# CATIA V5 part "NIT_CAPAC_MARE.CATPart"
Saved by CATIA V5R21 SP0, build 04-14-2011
Part number: NIT MARE
Publications: "Mating Face", "Axis"
Bounding box of the stored display mesh (mm): x -64.5 to 6.58, y -7.5 to 7.5, z -8.66 to 8.66
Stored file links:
  C:\Users\MIRCEA\Desktop\MOM\Mogan\model\NIT_CAPAC_MARE.CATPart
  C:\Program Files (x86)\Dassault Systemes\B21\intel_a\startup\components\MechanicalStandardParts\EN_Standards\Design_Tables\EN_ISO_4014_GRADES_A_B_HEXAGON_HEAD_BOLT.txt
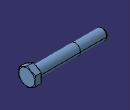
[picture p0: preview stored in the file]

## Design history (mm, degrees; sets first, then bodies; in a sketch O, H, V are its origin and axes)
Parameters
  d_dia = 10 mm
  l_length = 64.5 mm
  s_nom_across_flats = 15 mm
  k_max_head_depth = 6.58 mm
  dw_min = 14.5 mm
  r_min = 0.4 mm
  c_max = 0.6 mm
  p_pitch = 1.5 mm
  threading = 26 mm
Body1 "PartBody" (main body)
  Sketch1 on yz-plane, origin (0, 0, 0), H (0, 1, 0), V (0, 0, 1)
    circle A1 centre (0, 0) radius 7.25
    radius A1 = 7.25 {= dw_min /2}
  Pad1: profile Sketch1, direction (1, 0, 0), length 0.6 {= c_max}
  Sketch2 on face of Pad1, origin (0.6, 0, 0), H (0, 1, 0), V (0, 0, 1)
    point P1 (7.5, -4.3301)
    point P2 (7.5, 4.3301)
    point P3 (0, 8.6603)
    point P4 (-7.5, 4.3301)
    point P5 (-7.5, -4.3301)
    point P6 (0, -8.6603)
    point P7 (7.5, 0)
    line L1 (7.5, -4.3301) -> (7.5, 4.3301)
    line L2 (7.5, 4.3301) -> (0, 8.6603)
    line L3 (0, 8.6603) -> (-7.5, 4.3301)
    line L4 (-7.5, 4.3301) -> (-7.5, -4.3301)
    line L5 (-7.5, -4.3301) -> (0, -8.6603)
    line L6 (0, -8.6603) -> (7.5, -4.3301)
    construction line L7 (0, 0) -> (7.5, 0)
    construction circle A1 centre (0, 0) radius 8.6603
    construction arc A2 centre (-7.5, -4.3301) radius 8.6603 from (-7.5, 4.3301) to (0, -8.6603) cw
    construction arc A3 centre (7.5, 4.3301) radius 8.6603 from (0, 8.6603) to (7.5, -4.3301) ccw
    point P8 (-7.5, -4.3301)
    point P9 (7.5, 4.3301)
    distance L1 L4 = 15 {= s_nom_across_flats}
    horizontal: L7 H
    coincidence: A1 P1, A1 P2, A1 P3, A1 P4, A1 P5, A1 P6, A2 P4, A2 P6, A2 O, P8 P5, A3 P3, A3 P1, A3 O, P9 P2
    midpoint: P7 L1
  Pad2: profile Sketch2, direction (1, 0, 0), length 5.98 {= k_max_head_depth -c_max}
  Sketch3 on zx-plane, origin (0, 0, 0), H (-1, 0, 0), V (0, 0, 1)
    point P1 (-6.58, 7.4664)
    axis line L1 (-94.6904, 0) -> (76.7146, 0)
    reference intersected line E1 through (1000000, 0) direction (-1, 0) from xy-plane
    line L2 (-5.8907, 8.6603) -> (-6.58, 7.4664)
    line L3 (-5.8907, 8.6603) -> (-6.58, 8.6603)
    line L4 (-6.58, 8.6603) -> (-6.58, 7.4664)
    reference projected line E2 (-0.8, 8.6603) -> (-18.28, 8.6603) from edge [face of Pad2 | face of Pad2]
    distance P1 H = 7.4664 {= s_nom_across_flats /2.009}
    distance P1 V = 6.58 {= k_max_head_depth}
    angle L4 L2 = 30
    horizontal: L1 H, L3 H
    coincidence: L1 E1, L3 E2
    vertical: L4 V
  Groove1: profile Sketch3, axis Sketch3.L1, angle 360
  Sketch4 on face of Pad1, origin (0, 0, 0), H (0, -1, 0), V (0, 0, 1)
    circle A1 centre (0, 0) radius 5
    radius A1 = 5 {= d_dia /2}
  Pad3: profile Sketch4, direction (-1, 0, 0), length 38.5 {= l_length -threading}
  Sketch5 on face of Pad3, origin (-38.5, 0, 0), H (0, -1, 0), V (0, 0, 1)
    circle A1 centre (0, 0) radius 4.878
    radius A1 = 4.878 {= d_dia /2.05}
  Pad4: profile Sketch5, direction (-1, 0, 0), length 26 {= threading}
  Chamfer1: length 1.5 {= p_pitch}, angle 45, on face of Pad4
  Fillet1: radius 0.4 {= r_min}, on edge [face of Pad3 | face of Pad1]
  Thread1: diameter 9.7561 {= d_dia /1.025}, depth 26 {= threading}, pitch 1, on face of Pad4, from face of Pad4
